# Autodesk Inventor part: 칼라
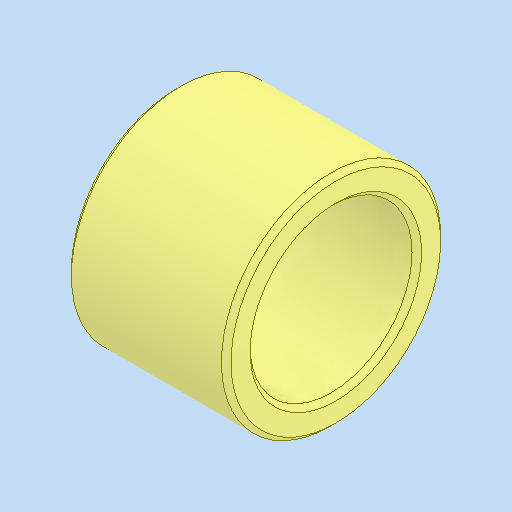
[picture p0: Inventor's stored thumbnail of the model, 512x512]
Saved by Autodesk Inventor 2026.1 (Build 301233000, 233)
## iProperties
Created: 2026-01
Part Number: 칼라
Material: 강철, 연강
Document SubType Name: Modeling
Designer: PC-30
Density: 7.85 g/cm^3
Appearance: 기본값
Author: jhkim
Sending System: Autodesk Inventor 2026
Preprocessor: ST-DEVELOPER v20.1
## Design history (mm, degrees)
feature "솔리드1"
node "솔리드2"
